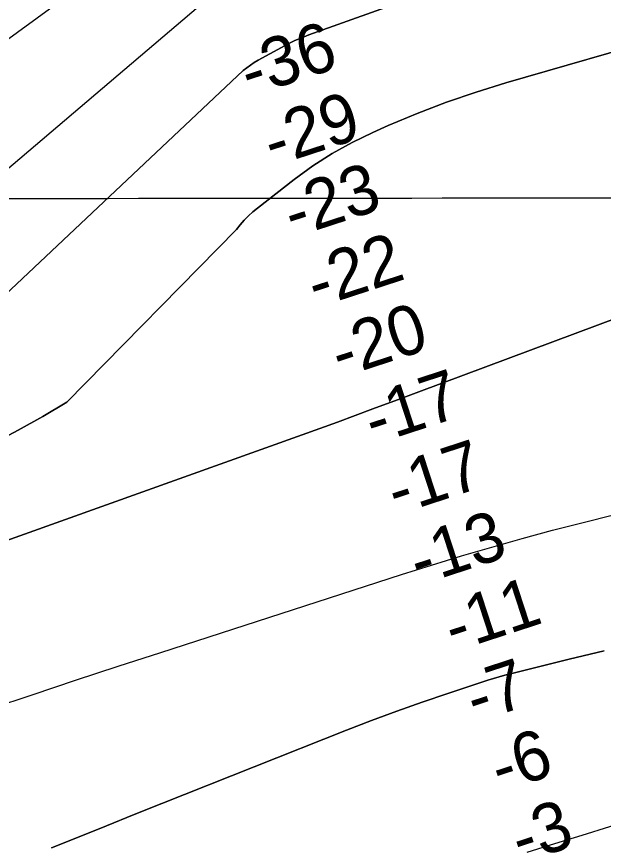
# Model space of a CAD drawing. Extents: x 3297753 to 3335611, y 652252 to 677623.
# Drawn here: x 3318384 to 3319178, y 659798 to 660921 of the extents above; entities that cross this region are included whole.
import ezdxf

# ---------------------------------------------------------------- set-up
doc = ezdxf.new("R2010")
doc.units = 0
for name, color, linetype in [('V-GRID-MAJR', 7, 'Continuous'), ('V-RIVR-EDGE', 7, 'Continuous'), ('V-RIVR-RANG', 7, 'Continuous'), ('V-RRAP-FSHR', 7, 'Continuous'), ('V-TOPO-DPTH', 7, 'Continuous'), ('V-TOPO-MAJR', 7, 'Continuous'), ('V-TOPO-MINR', 7, 'Continuous')]:
    doc.layers.add(name, color=color, linetype=linetype)

msp = doc.modelspace()

# ---------------------------------------------------------------- linework, layer by layer
at = {"layer": 'V-GRID-MAJR'}
msp.add_spline([(3301868.458, 660661.303), (3307127.238, 660664.745), (3312386.018, 660668.952), (3317644.7970000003, 660673.924), (3322903.575, 660679.66), (3328162.353, 660686.162), (3333421.129, 660693.428), (3333421.13, 660693.428)], degree=3, dxfattribs=at)
at = {"layer": 'V-RIVR-EDGE'}
msp.add_spline([(3319472.941637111, 662096.7930483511), (3319451.3588761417, 662084.8263787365), (3319431.435066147, 662073.2700910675), (3319412.763924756, 662065.4410623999), (3319386.63724047, 662059.7028894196), (3319355.1274208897, 662056.0504476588), (3319321.5328949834, 662047.4293521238), (3319286.6877502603, 662035.909960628), (3319261.790162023, 662024.3659716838), (3319253.9098886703, 662022.3130370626), (3319243.962332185, 662022.3376345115), (3319236.9110218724, 662020.2826501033), (3319220.298964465, 662007.0602372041), (3319214.062268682, 661999.2004617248), (3319197.881091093, 661992.6087282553), (3319174.651677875, 661985.2054549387), (3319135.249286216, 661974.5263003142), (3319095.8438198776, 661962.603701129), (3319061.8266133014, 661950.6677783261), (3319035.6896800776, 661940.7847901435), (3319017.017513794, 661932.5412799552), (3319004.1501385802, 661925.1123842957), (3318977.5966740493, 661914.4014579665), (3318949.3975821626, 661908.6684094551), (3318929.074664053, 661903.3303694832), (3318893.4067056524, 661894.2999168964), (3318836.1693099, 661878.6910544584), (3318802.1592775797, 661869.6565022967), (3318784.3232485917, 661864.3123129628), (3318761.0999847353, 661859.3959287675), (3318735.3744583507, 661848.2684711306), (3318707.1599930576, 661836.3181998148), (3318683.937754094, 661831.8162971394), (3318667.767850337, 661829.7838603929), (3318647.8604386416, 661824.8592770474), (3318612.1842810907, 661812.5129722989), (3318583.557384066, 661801.3926889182), (3318550.7836220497, 661789.4536914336), (3318517.189096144, 661780.8325958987), (3318486.906322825, 661770.5453751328), (3318459.104289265, 661757.7651158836), (3318437.1142210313, 661748.7008418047), (3318401.0928960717, 661732.5599758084), (3318376.26750918, 661719.6611275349), (3318350.3290856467, 661712.3999159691), (3318322.694633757, 661702.8889443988), (3318295.6167001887, 661690.5591544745), (3318275.8849717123, 661686.6635262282), (3318257.8395182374, 661681.0732629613), (3318243.7328864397, 661673.2193063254), (3318214.402406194, 661661.4585747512), (3318180.554292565, 661645.7645948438), (3318148.3966339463, 661630.066434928), (3318131.4656104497, 661619.4020199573), (3318111.1439235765, 661604.8015699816), (3318079.514916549, 661575.0148916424), (3318056.375804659, 661560.4214083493), (3318032.664847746, 661542.4484083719), (3318016.2987025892, 661532.346085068), (3317961.5347636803, 661489.6563784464), (3317862.7409676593, 661415.5201918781), (3317830.000317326, 661391.9346352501), (3317829.4284723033, 661388.5551185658), (3317827.160598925, 661382.925841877), (3317810.80142045, 661375.6409435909), (3317785.9690668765, 661359.9246703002), (3317761.132533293, 661342.5179419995), (3317743.6157314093, 661322.83916031), (3317726.093356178, 661300.9064386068), (3317708.570980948, 661278.9737169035), (3317696.7168958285, 661270.5507019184), (3317673.576390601, 661255.3937336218), (3317601.3165498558, 661201.4775203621), (3317560.671782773, 661171.7131354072), (3317529.070642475, 661153.1961571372), (3317513.8245006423, 661140.2736221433), (3317483.9026686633, 661117.2445838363), (3317464.1514334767, 661105.4601655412), (3317423.524779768, 661083.0210856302), (3317409.427901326, 661079.1115240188), (3317401.539111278, 661079.1310307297), (3317375.02187604, 661065.6728774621), (3317364.298940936, 661058.9375308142), (3317348.501854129, 661051.0877541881), (3317330.4591873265, 661046.6244609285), (3317307.322862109, 661033.1579476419), (3317289.2704419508, 661024.7502593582), (3317263.8829633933, 661012.4162894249), (3317240.770324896, 661008.5290211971), (3317230.0529631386, 661004.047614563), (3317228.3527547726, 661000.107399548), (3317221.5867547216, 660998.4336645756), (3317196.2118161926, 660991.1710596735), (3317170.2678193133, 660981.6559080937), (3317149.4105141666, 660978.3265515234), (3317103.1615504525, 660960.9727700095), (3317073.2689785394, 660949.7769167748), (3317034.3383531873, 660929.5875968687), (3316995.9726061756, 660909.9603686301), (3316948.0192540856, 660886.9759170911), (3316914.7401988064, 660873.5344838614), (3316885.9704168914, 660860.6453889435), (3316880.8879051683, 660856.1500489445), (3316871.2891533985, 660848.2849456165), (3316865.650123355, 660846.6084239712), (3316855.5073932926, 660846.6335040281), (3316850.436028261, 660846.6460440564), (3316844.222366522, 660840.4630357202), (3316839.713093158, 660839.9106974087), (3316835.7700914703, 660840.4839357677), (3316830.6889730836, 660836.5520807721), (3316818.8362813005, 660828.69255079), (3316813.7635229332, 660828.1416058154), (3316808.125886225, 660827.0285691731), (3316803.6180061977, 660827.0397158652), (3316796.8352861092, 660818.6041608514), (3316784.9798076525, 660809.6176608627), (3316774.8203575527, 660802.8809208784), (3316771.4227274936, 660796.127460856), (3316765.182592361, 660779.238237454), (3316755.5545805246, 660759.5399490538), (3316745.937715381, 660744.3495406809), (3316732.375061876, 660728.6054006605), (3316712.626613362, 660717.9479523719), (3316683.852651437, 660703.368402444), (3316676.521773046, 660701.1325758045), (3316664.6746546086, 660695.5269858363), (3316651.676879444, 660680.3449374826), (3316633.048434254, 660666.8672775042), (3316616.117410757, 660656.2028625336), (3316590.149727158, 660637.1084658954), (3316544.4238416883, 660603.4122259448), (3316509.995523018, 660580.9578193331), (3316472.7330592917, 660551.7485593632), (3316428.7101688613, 660523.1195044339), (3316390.324915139, 660495.6034861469), (3316363.7965332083, 660477.6374528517), (3316349.689901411, 660469.783496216), (3316341.225086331, 660464.7330312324), (3316335.0267512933, 660464.7483579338), (3316325.447506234, 660464.7720446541), (3316313.605961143, 660461.4203947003), (3316289.9284443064, 660456.9710348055), (3316257.21287403, 660443.5282082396), (3316237.472785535, 660436.2516699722), (3316207.013941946, 660423.9302400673), (3316177.1032566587, 660405.4090817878), (3316154.5332031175, 660393.0681451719), (3316131.949216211, 660375.0923585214), (3316110.5047393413, 660362.185150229), (3316095.268350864, 660353.2070102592), (3316080.0166356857, 660338.0305352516), (3316051.216200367, 660312.744770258), (3316013.9216899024, 660270.5753552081), (3315988.5035579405, 660245.8447151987), (3315960.258247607, 660217.1766468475), (3315939.932380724, 660200.8857418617), (3315925.8062422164, 660185.1429951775), (3315911.127765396, 660173.9095218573), (3315895.315351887, 660159.8614101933), (3315882.8838483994, 660145.8049385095), (3315867.6307398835, 660130.0649784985), (3315849.0106547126, 660119.968228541), (3315837.714481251, 660109.2898802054), (3315808.904292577, 660080.0597201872), (3315786.883790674, 660062.0825402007), (3315758.087535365, 660038.487230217), (3315733.80891344, 660018.825168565), (3315725.31623163, 660002.5050035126), (3315692.0065229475, 659976.6669002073), (3315659.8196042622, 659949.1355552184), (3315603.3596369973, 659904.1960885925), (3315571.1643582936, 659873.2838335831), (3315569.473903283, 659873.2880135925), (3315558.756541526, 659868.8066069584), (3315547.4729080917, 659863.1996236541), (3315527.70355953, 659844.0899003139), (3315506.252115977, 659828.365267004), (3315477.473974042, 659812.0952620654), (3315461.117582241, 659805.9373337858), (3315440.8014687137, 659793.5908238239), (3315429.5025085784, 659781.7855054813), (3315402.39670828, 659758.1860154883), (3315361.760301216, 659731.8025405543), (3315304.197050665, 659696.44510566), (3315255.6634935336, 659666.7002274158), (3315169.909272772, 659624.6506393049), (3315140.01252085, 659611.76433106), (3315123.6505557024, 659603.3524627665), (3315098.8209888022, 659588.7631594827), (3315044.633074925, 659551.1434245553), (3314989.866349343, 659507.3267479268), (3314954.285980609, 659474.7323979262), (3314933.969867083, 659462.3858879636), (3314926.0573903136, 659452.826149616), (3314915.8840068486, 659440.4545595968), (3314897.8106866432, 659423.5945962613), (3314866.750737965, 659396.0604645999), (3314844.7260560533, 659376.3928296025), (3314848.656517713, 659370.7482262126), (3314824.9511341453, 659355.0291662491), (3314801.817595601, 659342.6896229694), (3314762.319305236, 659320.8112413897), (3314730.157466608, 659303.4226264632), (3314710.9669297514, 659290.5098448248), (3314664.676165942, 659256.2515132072), (3314628.5615722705, 659235.4917416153), (3314603.161553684, 659218.0864066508), (3314584.5456485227, 659209.6801117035), (3314564.8194933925, 659208.0384234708), (3314555.7953733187, 659204.6798068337), (3314546.758713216, 659196.2498251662), (3314528.110761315, 659174.8833751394), (3314492.471872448, 659118.6226549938), (3314473.8183472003, 659095.0022649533), (3314450.6653019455, 659074.7739316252), (3314428.653160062, 659060.177661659), (3314423.004376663, 659054.5567449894), (3314416.2174765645, 659044.4307349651), (3314398.1441563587, 659027.5707716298), (3314375.555989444, 659007.9045299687), (3314366.533262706, 659005.1093983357), (3314353.566140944, 659002.3240200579), (3314347.3552658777, 658997.2679817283), (3314346.770880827, 658988.817100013), (3314351.264827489, 658983.1711032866), (3314350.679049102, 658974.1567365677), (3314342.759605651, 658961.7795732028), (3314329.21924553, 658955.0511932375), (3314311.714983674, 658940.4437765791), (3314309.9994486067, 658930.3052265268), (3314294.200968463, 658921.8919648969), (3314283.476640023, 658914.5931332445), (3314276.1248615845, 658903.9050315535), (3314272.7244448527, 658896.0246015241), (3314237.727067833, 658871.3176482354), (3314206.690805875, 658853.3627616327), (3314198.2329574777, 658851.1297216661), (3314192.0332291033, 658850.581563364), (3314180.188897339, 658846.1029434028), (3314172.27642057, 658836.5432050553), (3314164.3555837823, 658823.6025566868), (3314142.346228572, 658810.1332567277), (3314120.890605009, 658792.7181684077), (3314097.189401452, 658778.6895634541), (3314086.4594996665, 658769.1367917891), (3314082.4997779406, 658762.9482101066), (3314080.224937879, 658754.5015084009), (3314072.3250011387, 658750.0131350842), (3314036.7864324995, 658734.3233351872), (3314006.327588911, 658722.0019052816), (3313997.2978954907, 658716.3893486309), (3313939.7165315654, 658673.7066086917), (3313888.343256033, 658634.9529370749), (3313863.5011491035, 658615.29226876), (3313820.60522868, 658586.6604271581), (3313772.637943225, 658558.0411255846), (3313732.004322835, 658532.7846206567), (3313718.4597827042, 658524.3657856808), (3313711.127510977, 658521.5664740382), (3313702.6752359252, 658521.5873740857), (3313693.0890241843, 658518.7936357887), (3313674.475905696, 658511.5143108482), (3313646.823340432, 658494.6780342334), (3313626.498866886, 658478.9506142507), (3313619.7272934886, 658475.0229392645), (3313610.1215750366, 658464.3404109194), (3313605.0125899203, 658449.138855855), (3313597.1126531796, 658444.6504825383), (3313577.9151496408, 658428.9202758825), (3313554.7593177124, 658407.5649725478), (3313537.8046074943, 658387.3213125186), (3313525.3508106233, 658364.2490807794), (3313506.1115069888, 658331.6143240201), (3313489.716101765, 658309.6788156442)], degree=3, dxfattribs=at)
at = {"layer": 'V-RRAP-FSHR'}
msp.add_spline([(3320150.091, 662315.5710000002), (3320047.664, 662286.0730000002), (3319931.171, 662251.4420000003), (3319796.745, 662213.6190000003), (3319527.389, 662140.5510000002), (3319274.193, 662042.7370000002), (3319037.812, 661963.7270000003), (3318810.274, 661886.8160000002), (3318640.56, 661831.2630000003), (3318442.36, 661771.5080000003), (3318223.46, 661674.4170000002), (3318125.373, 661625.8860000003), (3317894.869, 661465.5510000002), (3317737.052, 661336.6740000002), (3317612.895, 661222.6820000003), (3317433.813, 661109.8930000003), (3317347.157, 661063.4030000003), (3317219.776, 661006.2670000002), (3317048.566, 660941.6820000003), (3316920.502, 660895.5560000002), (3316802.751, 660835.2480000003), (3316727.515, 660743.3250000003), (3316559.686, 660646.4110000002), (3316447.95, 660562.2680000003), (3316323.703, 660479.2110000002), (3316253.559, 660449.9440000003), (3316120.171, 660384.2440000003), (3315999.77, 660284.1680000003), (3315912.514, 660202.1160000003), (3315858.046, 660160.3560000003)], degree=3, dxfattribs=at)
at = {"layer": 'V-TOPO-DPTH'}
for points in [[(3319149.999666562, 661028.602167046), (3318779.32136317, 660895.8789038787), (3318769.8235613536, 660892.2144834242), (3318760.4619468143, 660888.249173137), (3318751.3046131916, 660883.8325281), (3318742.2834668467, 660879.1149932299), (3318710.6312834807, 660861.566808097), (3318705.35291752, 660858.4407261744), (3318700.205850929, 660855.1231295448), (3318695.255733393, 660851.5182608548), (3318690.4369152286, 660847.7218774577), (3318336.3833433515, 660514.7170960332)], [(3318336.3833433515, 660514.7170960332), (3318690.4369152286, 660847.7218774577), (3318695.255733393, 660851.5182608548), (3318700.205850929, 660855.1231295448), (3318705.35291752, 660858.4407261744), (3318710.6312834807, 660861.566808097), (3318742.2834668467, 660879.1149932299), (3318751.3046131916, 660883.8325281), (3318760.4619468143, 660888.249173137), (3318769.8235613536, 660892.2144834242), (3318779.32136317, 660895.8789038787), (3319149.999666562, 661028.602167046)], [(3319490.356686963, 660959.5725170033), (3319045.99259418, 660831.1088364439), (3319005.442206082, 660818.4973815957), (3318965.2797439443, 660804.817800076), (3318925.699170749, 660789.5360285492), (3318886.506523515, 660773.186130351), (3318865.9829919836, 660764.1358754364), (3318837.94212814, 660750.5064218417), (3318810.6885299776, 660735.5596592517), (3318784.615830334, 660718.6369331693), (3318759.33039637, 660700.3968980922), (3318709.6200828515, 660661.6542361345), (3318703.402639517, 660656.4606749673), (3318697.4400301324, 660651.0067625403), (3318691.8596716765, 660645.1623232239), (3318686.5341471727, 660639.0575326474), (3318681.546195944, 660632.6541917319), (3318451.743371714, 660398.9909910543), (3318419.1050756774, 660379.5426259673), (3318385.927129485, 660360.9597833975), (3318151.00184071, 660235.5286041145)], [(3318151.00184071, 660235.5286041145), (3318385.927129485, 660360.9597833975), (3318419.1050756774, 660379.5426259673), (3318451.743371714, 660398.9909910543), (3318681.546195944, 660632.6541917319), (3318686.5341471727, 660639.0575326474), (3318691.8596716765, 660645.1623232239), (3318697.4400301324, 660651.0067625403), (3318703.402639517, 660656.4606749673), (3318709.6200828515, 660661.6542361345), (3318759.33039637, 660700.3968980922), (3318784.615830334, 660718.6369331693), (3318810.6885299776, 660735.5596592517), (3318837.94212814, 660750.5064218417), (3318865.9829919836, 660764.1358754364), (3318886.506523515, 660773.186130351), (3318925.699170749, 660789.5360285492), (3318965.2797439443, 660804.817800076), (3319005.442206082, 660818.4973815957), (3319045.99259418, 660831.1088364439), (3319490.356686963, 660959.5725170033)], [(3319290.4827270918, 660548.1685916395), (3318927.880240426, 660413.1397114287), (3318920.692600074, 660410.46035783), (3318913.506167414, 660407.7777722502), (3318906.321546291, 660405.0903386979), (3318899.1381328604, 660402.3996731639), (3318865.8033912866, 660389.9007734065), (3318841.932931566, 660381.0144608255), (3318818.0350315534, 660372.2031135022), (3318794.095971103, 660363.5042140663), (3318770.129470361, 660354.8802798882), (3318178.3031653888, 660143.4917256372)], [(3318178.3031653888, 660143.4917256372), (3318770.129470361, 660354.8802798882), (3318794.095971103, 660363.5042140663), (3318818.0350315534, 660372.2031135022), (3318841.932931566, 660381.0144608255), (3318865.8033912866, 660389.9007734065), (3318899.1381328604, 660402.3996731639), (3318906.321546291, 660405.0903386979), (3318913.506167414, 660407.7777722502), (3318920.692600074, 660410.46035783), (3318927.880240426, 660413.1397114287), (3319290.4827270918, 660548.1685916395)], [(3318430.9846254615, 659795.8753866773), (3318468.288731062, 659810.9773474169), (3318505.6145986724, 659826.0251580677), (3318542.9731092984, 659840.9917435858), (3318580.353381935, 659855.9041790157), (3318830.0213500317, 659955.1917679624), (3318864.0457272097, 659968.3656497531), (3318898.22093156, 659981.1240329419), (3318932.622376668, 659993.2591682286), (3318967.174648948, 660004.9788049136), (3319021.369835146, 660022.8134481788), (3319028.962523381, 660025.2177951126), (3319036.5882424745, 660027.5074685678), (3319044.2635078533, 660029.625131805), (3319051.971804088, 660031.6281215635), (3319131.447128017, 660051.3285013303), (3319178.9749786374, 660062.8468112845)], [(3319178.9749786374, 660062.8468112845), (3319131.447128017, 660051.3285013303), (3319051.971804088, 660031.6281215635), (3319044.2635078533, 660029.625131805), (3319036.5882424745, 660027.5074685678), (3319028.962523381, 660025.2177951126), (3319021.369835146, 660022.8134481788), (3318967.174648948, 660004.9788049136), (3318932.622376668, 659993.2591682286), (3318898.22093156, 659981.1240329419), (3318864.0457272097, 659968.3656497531), (3318830.0213500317, 659955.1917679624), (3318580.353381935, 659855.9041790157), (3318542.9731092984, 659840.9917435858), (3318505.6145986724, 659826.0251580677), (3318468.288731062, 659810.9773474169), (3318430.9846254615, 659795.8753866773)]]:
    msp.add_lwpolyline(points, dxfattribs=at)
at = {"layer": 'V-TOPO-MAJR'}
msp.add_lwpolyline([(3318720.817692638, 661011.4595790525), (3318188.509325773, 660558.6403545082), (3318182.150746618, 660552.510837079), (3318175.5634786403, 660546.642379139), (3318168.7968627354, 660541.000081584), (3318161.7612249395, 660535.697024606), (3318154.5462392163, 660530.6201280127), (3318108.213597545, 660499.6928764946), (3318089.81858333, 660487.9796262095), (3318071.1142610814, 660476.810684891), (3318051.945976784, 660466.4582070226), (3318032.468384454, 660456.6500381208), (3317961.1691291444, 660422.6539129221), (3317905.584083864, 660396.7685561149), (3317849.699475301, 660371.5638561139), (3317793.365521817, 660347.3801413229), (3317736.7320050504, 660323.8770833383), (3317313.9280560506, 660152.9051854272)], dxfattribs=at)
at = {"layer": 'V-TOPO-MINR'}
for points in [[(3318685.700132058, 661119.0655922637), (3318020.7342811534, 660633.9725906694), (3318006.3907595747, 660624.243419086), (3317991.6088610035, 660615.1176558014), (3317976.350687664, 660606.7412162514), (3317398.843067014, 660284.8033257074)], [(3318336.3833433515, 660514.7170960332), (3318690.4369152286, 660847.7218774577), (3318695.255733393, 660851.5182608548), (3318700.205850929, 660855.1231295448), (3318705.35291752, 660858.4407261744), (3318710.6312834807, 660861.566808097), (3318742.2834668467, 660879.1149932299), (3318751.3046131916, 660883.8325281), (3318760.4619468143, 660888.249173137), (3318769.8235613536, 660892.2144834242), (3318779.32136317, 660895.8789038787), (3319149.999666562, 661028.602167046)], [(3318151.00184071, 660235.5286041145), (3318385.927129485, 660360.9597833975), (3318419.1050756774, 660379.5426259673), (3318451.743371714, 660398.9909910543), (3318681.546195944, 660632.6541917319), (3318686.5341471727, 660639.0575326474), (3318691.8596716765, 660645.1623232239), (3318697.4400301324, 660651.0067625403), (3318703.402639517, 660656.4606749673), (3318709.6200828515, 660661.6542361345), (3318759.33039637, 660700.3968980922), (3318784.615830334, 660718.6369331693), (3318810.6885299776, 660735.5596592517), (3318837.94212814, 660750.5064218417), (3318865.9829919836, 660764.1358754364), (3318886.506523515, 660773.186130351), (3318925.699170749, 660789.5360285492), (3318965.2797439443, 660804.817800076), (3319005.442206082, 660818.4973815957), (3319045.99259418, 660831.1088364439), (3319490.356686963, 660959.5725170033)], [(3318178.3031653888, 660143.4917256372), (3318770.129470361, 660354.8802798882), (3318794.095971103, 660363.5042140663), (3318818.0350315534, 660372.2031135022), (3318841.932931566, 660381.0144608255), (3318865.8033912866, 660389.9007734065), (3318899.1381328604, 660402.3996731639), (3318906.321546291, 660405.0903386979), (3318913.506167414, 660407.7777722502), (3318920.692600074, 660410.46035783), (3318927.880240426, 660413.1397114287), (3319290.4827270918, 660548.1685916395)], [(3318348.4789965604, 659984.4267706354), (3318406.0451254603, 660003.6930033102), (3318463.6562470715, 660022.8229294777), (3318521.33485775, 660041.7483958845), (3318579.05846114, 660060.5375557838), (3318904.580683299, 660165.8576601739), (3318945.202504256, 660178.6978959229), (3318985.9342288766, 660191.1703558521), (3319026.8308089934, 660203.0911520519), (3319067.8372927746, 660214.6441724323), (3319108.982391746, 660225.7014372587), (3319150.202341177, 660236.4657029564), (3319191.534566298, 660246.7904699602)], [(3319074.642498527, 659790.3188385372), (3319111.9225723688, 659801.9470858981), (3319149.2515221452, 659813.4174630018), (3319186.613055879, 659824.7825932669), (3319222.0614100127, 659835.4838509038), (3319277.2413357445, 659851.876629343), (3319332.5142793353, 659867.9440766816), (3319387.9267497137, 659883.523527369), (3319443.432237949, 659898.777646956), (3319837.973474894, 660005.3375449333), (3319855.8246980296, 660009.9116543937), (3319873.745527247, 660014.1754102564), (3319891.7707655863, 660017.9736357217), (3319909.8656100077, 660021.4615075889), (3319972.8587762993, 660032.7595306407), (3320020.502434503, 660041.0255223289), (3320068.20390131, 660048.929928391), (3320115.99208102, 660056.2919560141), (3320163.838069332, 660063.2923980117), (3320211.6911662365, 660070.252550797), (3320259.495925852, 660077.5206116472), (3320307.2281795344, 660085.2505345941), (3320354.9120959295, 660093.2883656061), (3320444.486903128, 660108.8332488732)], [(3318430.9846254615, 659795.8753866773), (3318468.288731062, 659810.9773474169), (3318505.6145986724, 659826.0251580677), (3318542.9731092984, 659840.9917435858), (3318580.353381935, 659855.9041790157), (3318830.0213500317, 659955.1917679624), (3318864.0457272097, 659968.3656497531), (3318898.22093156, 659981.1240329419), (3318932.622376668, 659993.2591682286), (3318967.174648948, 660004.9788049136), (3319021.369835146, 660022.8134481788), (3319028.962523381, 660025.2177951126), (3319036.5882424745, 660027.5074685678), (3319044.2635078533, 660029.625131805), (3319051.971804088, 660031.6281215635), (3319131.447128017, 660051.3285013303), (3319178.9749786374, 660062.8468112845)]]:
    msp.add_lwpolyline(points, dxfattribs=at)

# ---------------------------------------------------------------- texts
at = {"layer": 'V-RIVR-RANG'}
for s, p in [('-36', (3318698.803738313, 660812.2996696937)), ('-29', (3318730.3470250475, 660717.4031924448)), ('-23', (3318757.8781158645, 660621.1982605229)), ('-22', (3318789.1706403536, 660526.2199423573)), ('-20', (3318821.7169760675, 660431.6518287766)), ('-17', (3318866.8014240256, 660341.1747610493)), ('-17', (3318897.5924240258, 660246.0337610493)), ('-13', (3318927.881899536, 660150.7280792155)), ('-11', (3318974.972445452, 660060.9067388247)), ('-7', (3319004.5106342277, 659965.3555342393)), ('-6', (3319037.8092566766, 659871.03294341)), ('-3', (3319065.5911097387, 659774.9088524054))]:
    msp.add_text(s, height=67.00000000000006, rotation=18.07505555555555, dxfattribs=at).set_placement(p)

doc.saveas('drawing.dxf')
